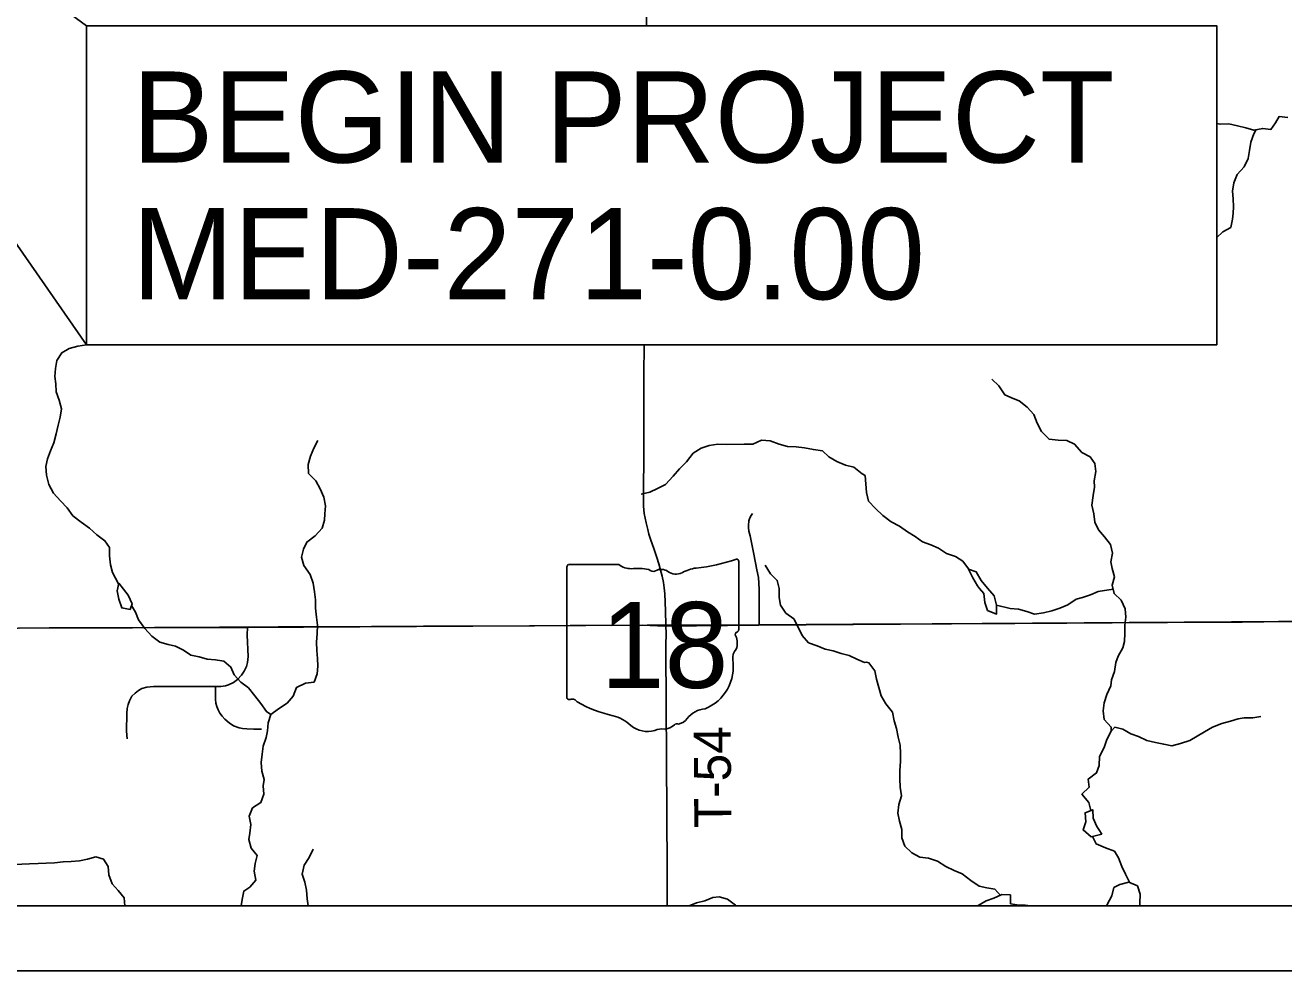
# Model space of a CAD drawing. Extents: x 0 to 34, y 0 to 22.
# Drawn here: x 3.395 to 5.327, y 14 to 15.452 of the extents above; entities that cross this region are included whole.
import ezdxf

# ---------------------------------------------------------------- set-up
doc = ezdxf.new("R2010")
doc.units = 0
for name, color, linetype in [('GM_X_Corporation', 7, 'Continuous'), ('GM_X_Minor_Lake', 7, 'Continuous'), ('GM_X_Minor_River', 7, 'Continuous'), ('GM_X_State_Location', 7, 'Continuous'), ('GM_X_State_Route', 7, 'Continuous'), ('GM_X_State_Shield', 7, 'Continuous'), ('GM_X_Township_Road', 7, 'Continuous'), ('GM_X_Township_Road_Text', 7, 'Continuous'), ('SH_Data', 7, 'Continuous'), ('SH_Text', 7, 'Continuous')]:
    doc.layers.add(name, color=color, linetype=linetype)

msp = doc.modelspace()

# ---------------------------------------------------------------- linework, layer by layer
at = {"layer": 'GM_X_Corporation'}
for points in [[(2.1, 20.9), (2.1, 14.1), (7.9734, 14.1), (7.9726, 14.5453), (7.9765, 15.2637), (7.9792, 15.5481), (7.979, 15.5988), (7.9808, 15.7192), (7.9807, 15.9078), (7.9821, 16.2487), (7.9825, 16.3395), (7.9818, 16.3982), (7.9825, 16.6077), (7.9838, 16.7968), (7.9877, 17.3871), (7.9891, 17.5498), (7.991, 17.7727), (7.9901, 18.1613)], [(5.4644, 14.5374), (4.5212, 14.531), (4.3772, 14.5296), (4.3422, 14.5307), (3.735, 14.5275), (3.3839, 14.5264)]]:
    msp.add_lwpolyline(points, dxfattribs=at)
msp.add_lwpolyline([(2.8649, 14.1), (7.9734, 14.1), (7.9726, 14.5453), (7.0871, 14.5429), (7.0197, 14.5427), (6.4941, 14.5412), (6.1476, 14.5397), (5.4644, 14.5374), (4.5212, 14.531), (4.3772, 14.5296), (4.3422, 14.5307), (3.735, 14.5275), (3.3839, 14.5264), (3.3511, 14.525), (2.8655, 14.5214), (2.8638, 14.4461)], close=True, dxfattribs=at)
at = {"layer": 'GM_X_Minor_Lake'}
for points in [[(4.886, 14.5617), (4.8822, 14.5757), (4.8719, 14.5879), (4.8624, 14.5996), (4.8548, 14.6126), (4.843, 14.6171), (4.8494, 14.6038), (4.8567, 14.5913), (4.86, 14.5873)], [(4.886, 14.5616), (4.8822, 14.5757), (4.8719, 14.5879), (4.8624, 14.5996), (4.8548, 14.6126), (4.843, 14.6171), (4.8494, 14.6038), (4.8567, 14.5913), (4.86, 14.5873)], [(3.5383, 14.5956), (3.5359, 14.5838), (3.5384, 14.571), (3.5428, 14.5574), (3.556, 14.555)], [(3.5382, 14.5953), (3.5359, 14.5838), (3.5384, 14.571), (3.5428, 14.5574), (3.556, 14.555)], [(3.556, 14.555), (3.5589, 14.5638), (3.553, 14.5769), (3.5382, 14.5953)], [(3.556, 14.555), (3.5589, 14.5638), (3.553, 14.5769), (3.5383, 14.5952)], [(4.86, 14.5873), (4.8666, 14.5795), (4.8678, 14.5658), (4.8723, 14.5536), (4.8861, 14.548), (4.886, 14.5617)], [(4.86, 14.5873), (4.8666, 14.5795), (4.8678, 14.5658), (4.8723, 14.5536), (4.8861, 14.548), (4.886, 14.5616)], [(5.043, 14.217), (5.0399, 14.2218), (5.0345, 14.2344), (5.0337, 14.2473), (5.022, 14.2427), (5.0231, 14.229), (5.0189, 14.2165), (5.0314, 14.2057)], [(5.043, 14.217), (5.0399, 14.2218), (5.0345, 14.2344), (5.0337, 14.2473), (5.022, 14.2427), (5.0231, 14.229), (5.0189, 14.2165), (5.0314, 14.2057)], [(5.0314, 14.2057), (5.0475, 14.2101), (5.043, 14.217)], [(5.0314, 14.2057), (5.0475, 14.2101), (5.043, 14.217)], [(5.0754, 14.1325), (5.0663, 14.1279), (5.0632, 14.115), (5.056, 14.1021), (5.0546, 14.1)], [(5.0754, 14.1325), (5.0663, 14.1279), (5.0632, 14.115), (5.056, 14.1021), (5.0546, 14.1)], [(5.1059, 14.1), (5.1059, 14.104), (5.1066, 14.1177), (5.1024, 14.1303), (5.0891, 14.136), (5.0754, 14.1325)], [(5.1059, 14.1), (5.1059, 14.104), (5.1066, 14.1177), (5.1024, 14.1303), (5.0891, 14.136), (5.0754, 14.1325)]]:
    msp.add_lwpolyline(points, dxfattribs=at)
at = {"layer": 'GM_X_Minor_River'}
for points in [[(5.3331, 15.3106), (5.3198, 15.3121), (5.3141, 15.3026), (5.3073, 15.2924), (5.2947, 15.2939), (5.281, 15.2912), (5.2689, 15.2946), (5.2559, 15.298), (5.2426, 15.301), (5.2293, 15.3002), (5.2242, 15.3014)], [(5.2847, 15.2919), (5.2811, 15.2855), (5.2765, 15.2729), (5.2746, 15.26), (5.2724, 15.2478), (5.2663, 15.2349), (5.2557, 15.2231), (5.2503, 15.2101), (5.2481, 15.1976), (5.2492, 15.1858), (5.2496, 15.1732), (5.2493, 15.1637), (5.2481, 15.1542), (5.2459, 15.1417), (5.2337, 15.1348), (5.2238, 15.1256)], [(3.5379, 14.5945), (3.5286, 14.6118), (3.5257, 14.6235), (3.5243, 14.6375), (3.5241, 14.6504), (3.5171, 14.6605), (3.5048, 14.6694), (3.4933, 14.6799), (3.4807, 14.6891), (3.468, 14.6988), (3.4591, 14.7111), (3.4487, 14.722), (3.4379, 14.7335), (3.4309, 14.7471), (3.4276, 14.7611), (3.4266, 14.7747), (3.4287, 14.7861), (3.4337, 14.7984), (3.4388, 14.811), (3.442, 14.8247), (3.4451, 14.838), (3.4483, 14.8506), (3.4504, 14.8632), (3.4467, 14.8764), (3.442, 14.8892), (3.4418, 14.9013), (3.4401, 14.9127), (3.441, 14.9252), (3.4434, 14.9374), (3.4508, 14.9493), (3.4624, 14.9556), (3.4755, 14.9596), (3.4887, 14.9614)], [(5.0621, 14.3683), (5.0621, 14.3744), (5.0514, 14.3858), (5.0499, 14.3991), (5.0514, 14.4116), (5.0552, 14.4242), (5.0616, 14.4375), (5.0627, 14.447), (5.0673, 14.4599), (5.0692, 14.4733), (5.0726, 14.4832), (5.0798, 14.4961), (5.0824, 14.5056), (5.0828, 14.5185), (5.0828, 14.5311), (5.0847, 14.5433), (5.0835, 14.5562), (5.0774, 14.5695), (5.0664, 14.5794), (5.0637, 14.5923), (5.0671, 14.6052), (5.0633, 14.6181), (5.0617, 14.628), (5.064, 14.6417), (5.0609, 14.6547), (5.0518, 14.6664), (5.0426, 14.6771), (5.0369, 14.6889), (5.0354, 14.7018), (5.0323, 14.7151), (5.0342, 14.7299), (5.0364, 14.7429), (5.036, 14.7527), (5.0387, 14.7668), (5.0368, 14.779), (5.0299, 14.7892), (5.017, 14.7961), (5.0059, 14.809), (4.9937, 14.8143), (4.9804, 14.815), (4.9667, 14.8165), (4.9553, 14.8283), (4.9484, 14.8412), (4.9431, 14.8545), (4.9331, 14.8656), (4.921, 14.8754), (4.9114, 14.8789), (4.8985, 14.8849), (4.8893, 14.8986), (4.8787, 14.9089)], [(3.7263, 14.1), (3.728, 14.1094), (3.7301, 14.1224), (3.7398, 14.1286), (3.7487, 14.1394), (3.7462, 14.153), (3.7475, 14.1648), (3.751, 14.177), (3.7418, 14.1886), (3.7378, 14.2018), (3.7395, 14.2113), (3.7411, 14.225), (3.7383, 14.2375), (3.7437, 14.2501), (3.7564, 14.2583), (3.7611, 14.2713), (3.7601, 14.2842), (3.7615, 14.2937), (3.7582, 14.3065), (3.7569, 14.3198), (3.7585, 14.3327), (3.7602, 14.3453), (3.7645, 14.3586), (3.7666, 14.3685), (3.7675, 14.3811), (3.7718, 14.3937), (3.7838, 14.4026), (3.7969, 14.4112), (3.8061, 14.422), (3.8112, 14.435), (3.8251, 14.4417), (3.8383, 14.4434), (3.843, 14.456), (3.8439, 14.4678), (3.8433, 14.4795), (3.8423, 14.4921), (3.8417, 14.5046), (3.843, 14.5183), (3.8436, 14.5308), (3.8418, 14.5433), (3.8404, 14.5569), (3.8402, 14.5698), (3.8389, 14.5819), (3.8367, 14.5956), (3.8324, 14.6088), (3.8227, 14.6226), (3.8187, 14.6351), (3.8222, 14.6477), (3.8269, 14.6584), (3.84, 14.6681), (3.8504, 14.68), (3.854, 14.6922), (3.8549, 14.7021), (3.8555, 14.7143), (3.8533, 14.7275), (3.8474, 14.7403), (3.8408, 14.7527), (3.8296, 14.7639), (3.829, 14.7776), (3.8329, 14.7902), (3.838, 14.8028), (3.8442, 14.8146)], [(4.6841, 14.761), (4.6796, 14.7632), (4.6669, 14.7733), (4.654, 14.7768), (4.641, 14.7823), (4.6284, 14.7893), (4.6188, 14.7986), (4.6048, 14.8006), (4.5911, 14.803), (4.5786, 14.8047), (4.565, 14.8052), (4.5524, 14.8088), (4.5387, 14.8139), (4.5251, 14.8152), (4.5116, 14.8089), (4.4987, 14.809), (4.4719, 14.8085), (4.4583, 14.8091), (4.4447, 14.8069), (4.4323, 14.8025), (4.4203, 14.7951), (4.4099, 14.7817), (4.3995, 14.7712), (4.3895, 14.7597), (4.378, 14.747), (4.3656, 14.7407), (4.3536, 14.7351), (4.3404, 14.7323)], [(4.6841, 14.761), (4.6864, 14.7344), (4.6895, 14.7215), (4.7001, 14.7101), (4.7116, 14.6995), (4.7241, 14.6896), (4.7371, 14.6828), (4.7493, 14.674), (4.7611, 14.6672), (4.7725, 14.6589), (4.7851, 14.6543), (4.7969, 14.6494), (4.8091, 14.641), (4.8228, 14.6365), (4.8342, 14.6293), (4.843, 14.6172)], [(4.6864, 14.4742), (4.6832, 14.4734), (4.6713, 14.4789), (4.6599, 14.4844), (4.6474, 14.4875), (4.6352, 14.4915), (4.623, 14.494), (4.6105, 14.499), (4.5975, 14.5038), (4.5875, 14.515), (4.5816, 14.5278), (4.5746, 14.5405), (4.5627, 14.5494), (4.5545, 14.5614), (4.5524, 14.5735), (4.5522, 14.5872), (4.5493, 14.5997), (4.5389, 14.6097), (4.5307, 14.6229)], [(4.886, 14.5617), (4.907, 14.5567), (4.9199, 14.5556), (4.9325, 14.5518), (4.9443, 14.548), (4.958, 14.5496), (4.9709, 14.553), (4.9834, 14.5572), (4.9956, 14.5622), (5.0085, 14.5709), (5.018, 14.5736), (5.0302, 14.5774), (5.042, 14.5828), (5.0649, 14.586)], [(3.7718, 14.3937), (3.7649, 14.3981), (3.7564, 14.4105), (3.7471, 14.4225), (3.7374, 14.4344), (3.7256, 14.4433), (3.7155, 14.4545), (3.7104, 14.4666), (3.6997, 14.4755), (3.6868, 14.4776), (3.6739, 14.4789), (3.6617, 14.4821), (3.6492, 14.4849), (3.6377, 14.4926), (3.6255, 14.4985), (3.6141, 14.5013), (3.6012, 14.5049), (3.5893, 14.5142), (3.5785, 14.5258), (3.5688, 14.5393), (3.564, 14.5509), (3.5578, 14.561)], [(4.6864, 14.4742), (4.6902, 14.4728), (4.699, 14.4606), (4.7017, 14.4481), (4.7051, 14.4352), (4.7089, 14.4222), (4.7162, 14.4101), (4.7261, 14.3972), (4.7288, 14.3842), (4.7322, 14.3724), (4.7349, 14.3591), (4.738, 14.3466), (4.7387, 14.3337), (4.7384, 14.3215), (4.7376, 14.3078), (4.7377, 14.2949), (4.7381, 14.2823), (4.74, 14.2686), (4.7362, 14.2557), (4.7347, 14.2424), (4.737, 14.2298), (4.7404, 14.2173), (4.7405, 14.2044), (4.745, 14.1914), (4.7561, 14.1812), (4.7683, 14.1747), (4.7816, 14.1732), (4.7953, 14.1683), (4.8082, 14.1603), (4.8208, 14.1543), (4.8334, 14.1489), (4.8467, 14.1387), (4.8593, 14.13), (4.8711, 14.1277), (4.8836, 14.1254), (4.8924, 14.1152)], [(5.0621, 14.3683), (5.0674, 14.374), (5.08, 14.371), (5.0922, 14.3641), (5.104, 14.36), (5.1169, 14.3539), (5.1302, 14.3505), (5.1428, 14.3479), (5.155, 14.3456), (5.1687, 14.3494), (5.1827, 14.3536), (5.2055, 14.3673), (5.2177, 14.3742), (5.2318, 14.3799), (5.2451, 14.3837), (5.2569, 14.3868), (5.2664, 14.3887), (5.2793, 14.3887), (5.2919, 14.3906)], [(5.0308, 14.2462), (5.0276, 14.2587), (5.017, 14.2713), (5.0284, 14.2819), (5.0268, 14.2945), (5.0397, 14.304), (5.0435, 14.3154), (5.0439, 14.3291), (5.0515, 14.3428), (5.0556, 14.3553), (5.0621, 14.3683)], [(5.0906, 14.1352), (5.0841, 14.1485), (5.0784, 14.1603), (5.0734, 14.1736), (5.0669, 14.1838), (5.0532, 14.1888), (5.0388, 14.1948), (5.0332, 14.2062)], [(3.8293, 14.1), (3.8275, 14.1108), (3.8265, 14.1237), (3.824, 14.1362), (3.82, 14.1486), (3.8228, 14.1623), (3.8309, 14.1742), (3.8367, 14.1869)], [(3.5474, 14.1), (3.5468, 14.112), (3.5375, 14.1232), (3.5283, 14.1336), (3.5231, 14.1472), (3.5221, 14.1601), (3.5151, 14.1717), (3.5033, 14.1753), (3.4905, 14.1713), (3.4781, 14.1692), (3.4652, 14.1678), (3.4528, 14.1672), (3.4399, 14.1659), (3.4267, 14.1656), (3.4146, 14.1647), (3.4014, 14.1644), (3.3893, 14.1638), (3.3764, 14.1632), (3.3636, 14.1615), (3.3504, 14.1616)], [(4.4141, 14.1), (4.4252, 14.1042), (4.438, 14.1074), (4.4504, 14.1126), (4.4603, 14.1139), (4.4728, 14.1103), (4.4851, 14.1007), (4.4863, 14.1)], [(4.9384, 14.1), (4.9301, 14.1008), (4.9206, 14.1011), (4.9076, 14.103), (4.9072, 14.1167), (4.8943, 14.1171), (4.8821, 14.1114), (4.87, 14.1075), (4.8578, 14.1003), (4.8567, 14.1)]]:
    msp.add_lwpolyline(points, dxfattribs=at)
at = {"layer": 'GM_X_State_Route'}
msp.add_lwpolyline([(3.3859, 14.5264), (3.4315, 14.5266), (3.4703, 14.5268), (3.5931, 14.5274), (3.6931, 14.528), (3.7359, 14.5279), (3.7831, 14.5281), (3.8475, 14.5284), (3.9262, 14.5288), (4.006, 14.5292), (4.1767, 14.5301), (4.2315, 14.5304), (4.3495, 14.5308), (4.3783, 14.5308), (4.5218, 14.5315), (4.6653, 14.5322), (4.7874, 14.5329), (4.8167, 14.533), (4.8641, 14.5333), (4.9143, 14.5336), (4.941, 14.5338), (4.9676, 14.5339), (4.9941, 14.5341), (5.0207, 14.5343), (5.042, 14.5345), (5.0633, 14.5346), (5.0899, 14.5348), (5.1165, 14.535), (5.1484, 14.5352), (5.1783, 14.5354), (5.2054, 14.5355), (5.2361, 14.5356), (5.2632, 14.5357), (5.2966, 14.5358), (5.4176, 14.5369)], dxfattribs=at)
at = {"layer": 'GM_X_State_Shield'}
for p, q in [((4.4902, 14.5242), (4.4902, 14.6289)), ((4.2265, 14.6205), (4.2265, 14.4204)), ((4.3063, 14.6239), (4.2291, 14.6239)), ((4.4901, 14.5242), (4.4902, 14.5242))]:
    msp.add_line(p, q, dxfattribs=at)
for centre, radius, start, end in [((4.3962, 14.8968), 0.2796, 275.8445, 288.9065), ((4.4872, 14.6293), 0.00294, 351.8621, 97.738), ((4.2295, 14.6209), 0.00305, 98.1301, 188.1301), ((4.3247, 14.6472), 0.0296, 231.6195, 271.1119), ((4.3345, 14.5116), 0.1064, 80.4867, 94.9883), ((4.3587, 14.622), 0.00855, 219.7921, 297.1024), ((4.3712, 14.5988), 0.0178, 54.4667, 119.1411), ((4.3941, 14.6306), 0.0214, 233.8562, 294.8282), ((4.4319, 14.5628), 0.0563, 97.3462, 120.7689), ((4.4895, 14.5165), 0.00454, 107.944, 210.337), ((4.4606, 14.5033), 0.0273, 340.033, 23.6496), ((4.487, 14.5238), 0.00314, 289.6038, 7.7341), ((4.5007, 14.4804), 0.0198, 136.8065, 186.9296), ((4.4119, 14.4671), 0.0699, 292.3089, 8.9858), ((4.2295, 14.4199), 0.00308, 171.9584, 258.3066), ((4.23, 14.4404), 0.0235, 267.339, 280.6039), ((4.2348, 14.4088), 0.00848, 29.7484, 93.2717), ((4.3419, 14.5886), 0.2019, 240.4129, 257.1985), ((4.4414, 14.3642), 0.0383, 94.4031, 142.5768), ((4.2817, 14.3305), 0.0632, 47.1842, 75.836), ((4.3761, 14.3928), 0.0214, 268.777, 315.5493), ((4.3954, 14.3735), 0.00601, 65.7517, 132.6484), ((4.3929, 14.401), 0.0226, 282.8732, 323.2771), ((4.35, 14.4078), 0.0401, 230.7004, 286.2918), ((4.3732, 14.3386), 0.0329, 85.6951, 111.2099)]:
    msp.add_arc(centre, radius, start, end, dxfattribs=at)
at = {"layer": 'GM_X_Township_Road'}
for points in [[(4.3485, 15.4514), (4.3489, 15.4809), (4.3498, 15.5312), (4.3506, 15.5634), (4.3529, 15.6445), (4.3536, 15.673), (4.3545, 15.7102), (4.3549, 15.7299), (4.3556, 15.7585), (4.3561, 15.7785), (4.358, 15.8728)], [(4.3442, 14.7557), (4.3443, 14.7727), (4.3445, 14.8278), (4.3446, 14.9154), (4.3448, 14.9614)], [(4.3783, 14.5308), (4.3777, 14.5531), (4.3769, 14.5791), (4.3757, 14.5882), (4.3745, 14.5963), (4.3725, 14.6062), (4.3697, 14.6172), (4.3674, 14.6252), (4.3643, 14.6346), (4.3598, 14.6488), (4.3553, 14.6615), (4.3524, 14.6705), (4.3505, 14.6776), (4.3479, 14.688), (4.3463, 14.6954), (4.3451, 14.7026), (4.3443, 14.7078), (4.3439, 14.7137), (4.344, 14.7267), (4.3442, 14.7557)], [(4.5218, 14.5315), (4.5215, 14.5857), (4.5213, 14.5955), (4.5204, 14.6041), (4.5182, 14.6158), (4.5132, 14.6401), (4.5075, 14.668), (4.5059, 14.6752), (4.5052, 14.6807), (4.505, 14.684), (4.5058, 14.6911), (4.5073, 14.6956), (4.5092, 14.6992), (4.5112, 14.7023)], [(3.5511, 14.3562), (3.5501, 14.368), (3.5506, 14.3952), (3.5511, 14.4029), (3.5526, 14.4092), (3.5547, 14.4149), (3.5586, 14.4216), (3.5634, 14.4266), (3.5687, 14.4307), (3.5736, 14.4334), (3.5815, 14.4359), (3.5916, 14.4368), (3.6112, 14.4367), (3.647, 14.4368), (3.6871, 14.4367), (3.695, 14.4368), (3.702, 14.4377), (3.7067, 14.4392), (3.7145, 14.4428), (3.7207, 14.4475), (3.7268, 14.4541), (3.7308, 14.4604), (3.7342, 14.4672), (3.7359, 14.4733), (3.7369, 14.4826), (3.7355, 14.5155), (3.7359, 14.5279)], [(4.3785, 14.501), (4.3787, 14.517), (4.3783, 14.5308)], [(4.3805, 14.1), (4.3803, 14.1559), (4.3785, 14.4941), (4.3785, 14.501)], [(3.6871, 14.4367), (3.6869, 14.4174), (3.6875, 14.4109), (3.6891, 14.406), (3.691, 14.4008), (3.6936, 14.3958), (3.6971, 14.391), (3.7012, 14.3863), (3.7076, 14.3809), (3.7145, 14.3765), (3.723, 14.3734), (3.7284, 14.3721), (3.7348, 14.3715), (3.7455, 14.3714), (3.7577, 14.3714)]]:
    msp.add_lwpolyline(points, dxfattribs=at)
at = {"layer": 'SH_Data'}
for p, q in [((2.1, 14.1), (8.9, 14.1)), ((2, 14), (9, 14))]:
    msp.add_line(p, q, dxfattribs=at)
at = {"layer": 'SH_Text'}
for points in [[(3.4887, 15.4514), (2.7956, 15.9593), (3.4887, 14.9614)], [(3.4887, 14.9614), (5.2242, 14.9614), (5.2242, 15.4514), (3.4887, 15.4514)]]:
    msp.add_lwpolyline(points, close=True, dxfattribs=at)

# ---------------------------------------------------------------- texts
at = {"layer": 'GM_X_State_Location'}
for s, p in [('s', (4.3554, 14.5071)), ('r', (4.3553, 14.5071))]:
    msp.add_text(s, height=0.000189, dxfattribs=at).set_placement(p)
msp.add_text('18', height=0.000189, rotation=0, dxfattribs=at).set_placement((4.3077, 14.4934))
at = {"layer": 'GM_X_State_Shield'}
msp.add_text('18', height=0.13184, dxfattribs=at).set_placement((4.2782, 14.4345))
at = {"layer": 'GM_X_Township_Road_Text'}
msp.add_text('T-54', height=0.05682, rotation=90.3535, dxfattribs=at).set_placement((4.4788, 14.2195))
at = {"layer": 'SH_Text'}
for s, p in [('BEGIN PROJECT', (3.5587, 15.2414)), ('MED-271-0.00', (3.5587, 15.0314))]:
    msp.add_text(s, height=0.14, dxfattribs=at).set_placement(p)

doc.saveas('drawing.dxf')
